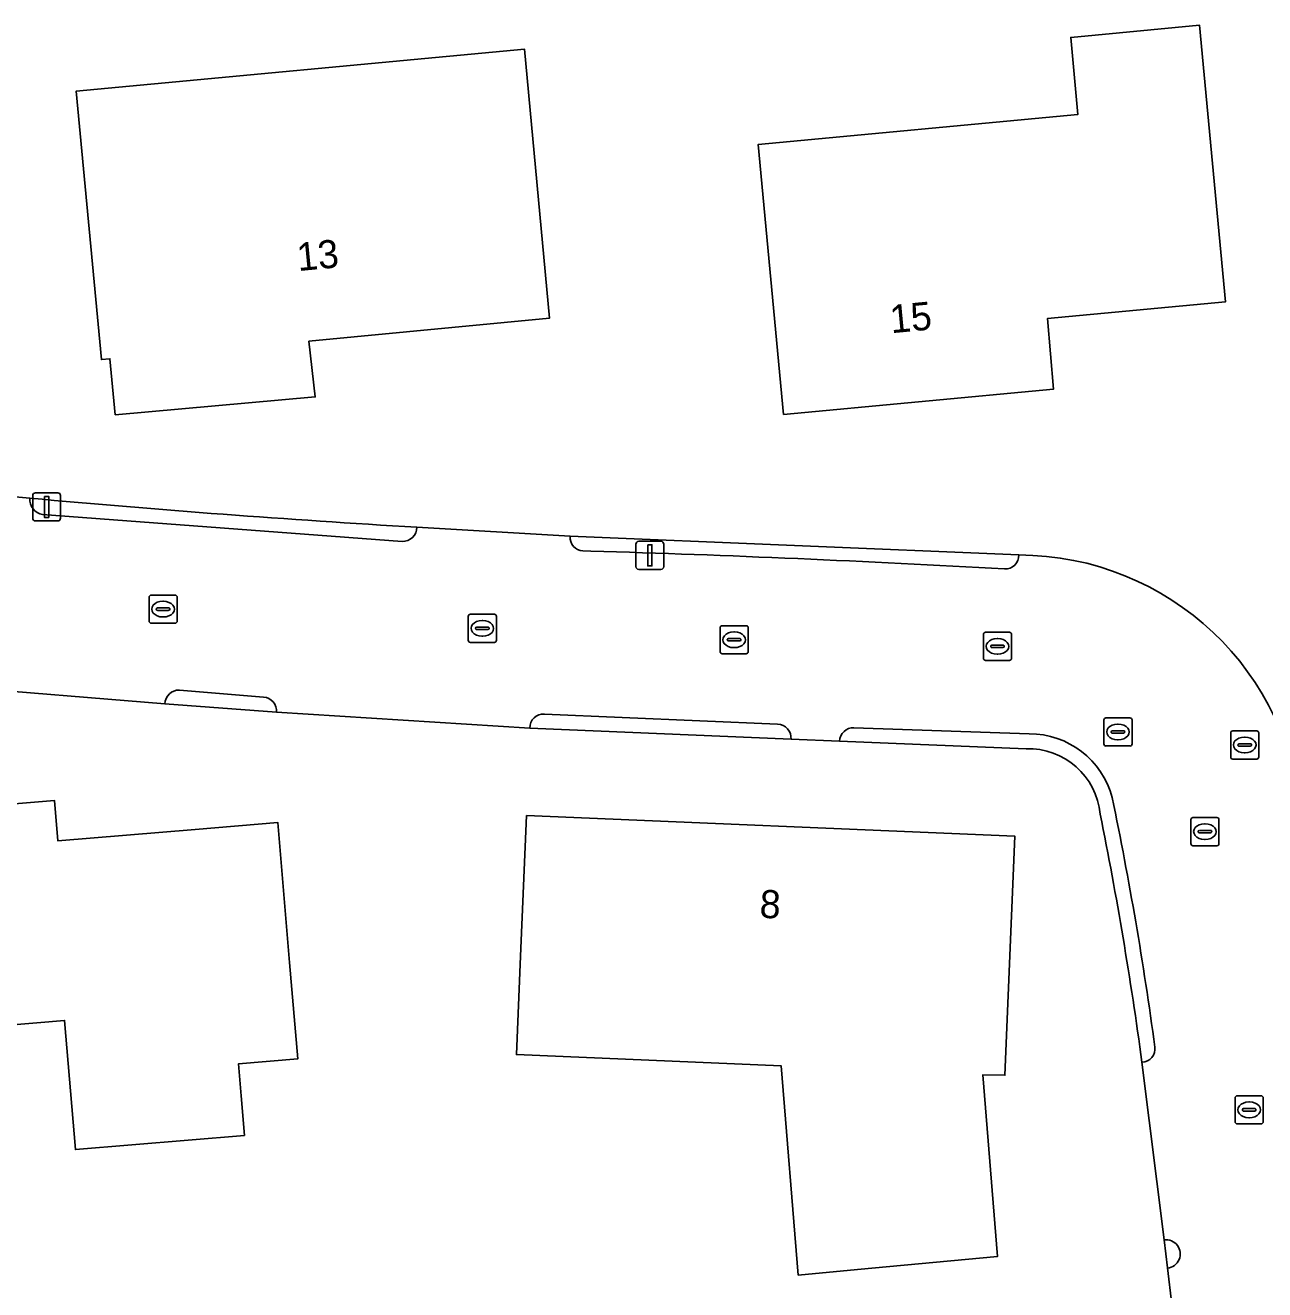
# Model space of a CAD drawing. Extents: x 162156 to 163172, y 378995 to 380779.
# Drawn here: x 162380.59 to 162424.68, y 380662.76 to 380707.74 of the extents above; entities that cross this region are included whole.
import ezdxf

# ---------------------------------------------------------------- set-up
doc = ezdxf.new("R2010")
doc.units = 0
for name, color, linetype in [('IMGEO_Brandkraan', 7, 'Continuous'), ('IMGEO_Erf', 7, 'Continuous'), ('IMGEO_Kolk', 7, 'Continuous'), ('IMGEO_Lichtmast', 7, 'Continuous'), ('IMGEO_Pand', 7, 'Continuous'), ('IMGEO_Pand_nummerreeks', 7, 'Continuous'), ('IMGEO_Rijbaan_lokaal_open', 7, 'Continuous'), ('IMGEO_Rioolput', 7, 'Continuous'), ('IMGEO_Voetpad_open', 7, 'Continuous')]:
    doc.layers.add(name, color=color, linetype=linetype)

msp = doc.modelspace()

# ---------------------------------------------------------------- linework, layer by layer
at = {"layer": 'IMGEO_Brandkraan'}
for p, q in [((162423.466, 380681.714), (162423.466, 380682.566)), ((162423.541, 380682.64), (162424.393, 380682.64)), ((162423.954, 380682.42), (162423.979, 380682.42)), ((162424.467, 380682.566), (162424.467, 380681.714)), ((162423.725, 380682.134), (162423.725, 380682.146)), ((162424.163, 380682.097), (162423.765, 380682.097)), ((162423.768, 380682.183), (162424.166, 380682.183)), ((162423.977, 380681.86), (162423.952, 380681.86)), ((162424.209, 380682.146), (162424.209, 380682.134)), ((162424.393, 380681.64), (162423.541, 380681.64))]:
    msp.add_line(p, q, dxfattribs=at)
for points in [[(162423.466, 380681.714), (162423.466, 380682.566)], [(162423.541, 380682.64), (162424.393, 380682.64)], [(162424.467, 380682.566), (162424.467, 380681.714)], [(162424.393, 380681.64), (162423.541, 380681.64)]]:
    msp.add_lwpolyline(points, dxfattribs=at)
for centre, radius, start, end in [((162423.543, 380682.564), 0.0765, 91.552, 178.448), ((162423.543, 380682.564), 0.0765, 91.552, 178.448), ((162424.391, 380682.564), 0.0765, 1.552, 88.448), ((162424.391, 380682.564), 0.0765, 1.552, 88.448), ((162423.765, 380682.143), 0.0403, 85.8775, 175.7526), ((162423.762, 380682.133), 0.0366, 178.938, 274.7102), ((162424.166, 380682.14), 0.043, 264.8664, 352.4533), ((162424.17, 380682.145), 0.0386, 1.7309, 96.639), ((162423.543, 380681.716), 0.0765, 181.552, 268.448), ((162423.543, 380681.716), 0.0765, 181.552, 268.448), ((162424.391, 380681.716), 0.0765, 271.552, 358.448), ((162424.391, 380681.716), 0.0765, 271.552, 358.448)]:
    msp.add_arc(centre, radius, start, end, dxfattribs=at)
for centre, major_axis, ratio, start_param, end_param in [((162423.953, 380682.14), (-0.387, 0.002), 0.722429, 4.712389, 7.853982), ((162423.978, 380682.14), (-0.39, 0.002), 0.717154, 1.570796, 4.712389)]:
    msp.add_ellipse(centre, major_axis=major_axis, ratio=ratio, start_param=start_param, end_param=end_param, dxfattribs=at)
at = {"layer": 'IMGEO_Erf'}
for points in [[(162407.558, 380693.891), (162406.654, 380703.498), (162418.034, 380704.571), (162417.777, 380707.309), (162422.357, 380707.741), (162423.284, 380697.905), (162416.947, 380697.307), (162417.161, 380694.796)], [(162383.783, 380693.889), (162383.596, 380695.878), (162383.297, 380695.85), (162382.401, 380705.401), (162398.341, 380706.895), (162399.237, 380697.323), (162390.677, 380696.5), (162390.903, 380694.519)], [(162370.147, 380671.342), (162369.798, 380675.489), (162369.378, 380680.471), (162377.536, 380681.174), (162377.649, 380679.832), (162381.627, 380680.167), (162381.749, 380678.726), (162386.632, 380679.138), (162389.571, 380679.386), (162389.991, 380674.404), (162390.28, 380670.974), (162388.167, 380670.796), (162388.262, 380669.663), (162388.382, 380668.252), (162382.372, 380667.746), (162381.985, 380672.339)], [(162407.472, 380670.727), (162398.06, 380671.123), (162398.208, 380674.63), (162398.418, 380679.625), (162415.79, 380678.893), (162415.435, 380670.393), (162414.646, 380670.4), (162415.167, 380663.941), (162410.189, 380663.479), (162408.083, 380663.283)]]:
    msp.add_lwpolyline(points, close=True, dxfattribs=at)
for points in [[(162376.382, 380691.307), (162380.755, 380690.919)], [(162394.515, 380689.886), (162399.974, 380689.562), (162415.928, 380688.898)], [(162416.186, 380682.008), (162409.556, 380682.276), (162407.826, 380682.346), (162398.541, 380682.743), (162389.525, 380683.301), (162385.556, 380683.6), (162378.006, 380684.221)], [(162421.368, 380662.235), (162421.22, 380663.534), (162421.1, 380664.53), (162420.311, 380670.851)]]:
    msp.add_lwpolyline(points, dxfattribs=at)
for centre, radius, start, end in [((162419.09, 381109.397), 420.23, 264.76598, 266.64743), ((162415.913, 380678.811), 10.087, 3.3743, 89.9136), ((162416.259, 380679.433), 2.576, 5.4978, 91.6247), ((162284.383, 380652.482), 137.163, 7.69611, 11.43684)]:
    msp.add_arc(centre, radius, start, end, dxfattribs=at)
at = {"layer": 'IMGEO_Kolk'}
for p, q in [((162384.99, 380686.546), (162384.99, 380687.398)), ((162385.065, 380687.472), (162385.917, 380687.472)), ((162385.478, 380687.252), (162385.503, 380687.252)), ((162385.991, 380687.398), (162385.991, 380686.546)), ((162385.249, 380686.966), (162385.249, 380686.978)), ((162385.687, 380686.929), (162385.289, 380686.929)), ((162385.292, 380687.015), (162385.69, 380687.015)), ((162385.733, 380686.978), (162385.733, 380686.966)), ((162396.422, 380686.788), (162397.274, 380686.788)), ((162385.917, 380686.472), (162385.065, 380686.472)), ((162385.501, 380686.692), (162385.476, 380686.692)), ((162396.347, 380685.862), (162396.347, 380686.714)), ((162396.606, 380686.282), (162396.606, 380686.294)), ((162396.649, 380686.331), (162397.047, 380686.331)), ((162396.835, 380686.568), (162396.86, 380686.568)), ((162397.09, 380686.294), (162397.09, 380686.282)), ((162397.348, 380686.714), (162397.348, 380685.862)), ((162405.302, 380685.456), (162405.302, 380686.308)), ((162405.377, 380686.382), (162406.229, 380686.382)), ((162406.303, 380686.308), (162406.303, 380685.456)), ((162397.044, 380686.245), (162396.646, 380686.245)), ((162396.858, 380686.008), (162396.833, 380686.008)), ((162405.561, 380685.876), (162405.561, 380685.888)), ((162405.999, 380685.839), (162405.601, 380685.839)), ((162405.604, 380685.925), (162406.002, 380685.925)), ((162405.79, 380686.162), (162405.815, 380686.162)), ((162406.045, 380685.888), (162406.045, 380685.876)), ((162414.67, 380685.221), (162414.67, 380686.073)), ((162414.745, 380686.147), (162415.597, 380686.147)), ((162415.158, 380685.927), (162415.183, 380685.927)), ((162415.671, 380686.073), (162415.671, 380685.221)), ((162397.274, 380685.788), (162396.422, 380685.788)), ((162406.229, 380685.382), (162405.377, 380685.382)), ((162405.813, 380685.602), (162405.788, 380685.602)), ((162414.929, 380685.641), (162414.929, 380685.653)), ((162415.367, 380685.604), (162414.969, 380685.604)), ((162414.972, 380685.69), (162415.37, 380685.69)), ((162415.181, 380685.367), (162415.156, 380685.367)), ((162415.413, 380685.653), (162415.413, 380685.641)), ((162415.597, 380685.147), (162414.745, 380685.147)), ((162422.124, 380679.557), (162422.976, 380679.557)), ((162422.049, 380678.631), (162422.049, 380679.483)), ((162422.351, 380679.1), (162422.749, 380679.1)), ((162422.537, 380679.337), (162422.562, 380679.337)), ((162423.05, 380679.483), (162423.05, 380678.631)), ((162422.308, 380679.051), (162422.308, 380679.063)), ((162422.746, 380679.014), (162422.348, 380679.014)), ((162422.56, 380678.777), (162422.535, 380678.777)), ((162422.792, 380679.063), (162422.792, 380679.051)), ((162422.976, 380678.557), (162422.124, 380678.557)), ((162423.698, 380669.66), (162424.55, 380669.66)), ((162423.623, 380668.734), (162423.623, 380669.586)), ((162423.925, 380669.203), (162424.323, 380669.203)), ((162424.111, 380669.44), (162424.136, 380669.44)), ((162424.624, 380669.586), (162424.624, 380668.734)), ((162423.882, 380669.154), (162423.882, 380669.166)), ((162424.32, 380669.117), (162423.922, 380669.117)), ((162424.134, 380668.88), (162424.109, 380668.88)), ((162424.366, 380669.166), (162424.366, 380669.154)), ((162424.55, 380668.66), (162423.698, 380668.66))]:
    msp.add_line(p, q, dxfattribs=at)
for points in [[(162384.99, 380686.546), (162384.99, 380687.398)], [(162385.065, 380687.472), (162385.917, 380687.472)], [(162385.991, 380687.398), (162385.991, 380686.546)], [(162396.422, 380686.788), (162397.274, 380686.788)], [(162385.917, 380686.472), (162385.065, 380686.472)], [(162396.347, 380685.862), (162396.347, 380686.714)], [(162397.348, 380686.714), (162397.348, 380685.862)], [(162405.302, 380685.456), (162405.302, 380686.308)], [(162405.377, 380686.382), (162406.229, 380686.382)], [(162406.303, 380686.308), (162406.303, 380685.456)], [(162414.67, 380685.221), (162414.67, 380686.073)], [(162414.745, 380686.147), (162415.597, 380686.147)], [(162415.671, 380686.073), (162415.671, 380685.221)], [(162397.274, 380685.788), (162396.422, 380685.788)], [(162406.229, 380685.382), (162405.377, 380685.382)], [(162415.597, 380685.147), (162414.745, 380685.147)], [(162422.124, 380679.557), (162422.976, 380679.557)], [(162422.049, 380678.631), (162422.049, 380679.483)], [(162423.05, 380679.483), (162423.05, 380678.631)], [(162422.976, 380678.557), (162422.124, 380678.557)], [(162423.698, 380669.66), (162424.55, 380669.66)], [(162423.623, 380668.734), (162423.623, 380669.586)], [(162424.624, 380669.586), (162424.624, 380668.734)], [(162424.55, 380668.66), (162423.698, 380668.66)]]:
    msp.add_lwpolyline(points, dxfattribs=at)
for centre, radius, start, end in [((162385.067, 380687.396), 0.0765, 91.552, 178.448), ((162385.067, 380687.396), 0.0765, 91.552, 178.448), ((162385.915, 380687.396), 0.0765, 1.552, 88.448), ((162385.915, 380687.396), 0.0765, 1.552, 88.448), ((162385.289, 380686.975), 0.0403, 85.8775, 175.7526), ((162385.286, 380686.965), 0.0366, 178.938, 274.7102), ((162385.69, 380686.972), 0.043, 264.8664, 352.4533), ((162385.694, 380686.977), 0.0386, 1.7309, 96.639), ((162396.424, 380686.712), 0.0765, 91.552, 178.448), ((162396.424, 380686.712), 0.0765, 91.552, 178.448), ((162397.272, 380686.712), 0.0765, 1.552, 88.448), ((162397.272, 380686.712), 0.0765, 1.552, 88.448), ((162385.067, 380686.548), 0.0765, 181.552, 268.448), ((162385.067, 380686.548), 0.0765, 181.552, 268.448), ((162385.915, 380686.548), 0.0765, 271.552, 358.448), ((162385.915, 380686.548), 0.0765, 271.552, 358.448), ((162396.646, 380686.291), 0.0403, 85.8775, 175.7526), ((162396.643, 380686.281), 0.0366, 178.938, 274.7102), ((162397.047, 380686.288), 0.043, 264.8664, 352.4533), ((162397.051, 380686.293), 0.0386, 1.7309, 96.639), ((162405.379, 380686.306), 0.0765, 91.552, 178.448), ((162405.379, 380686.306), 0.0765, 91.552, 178.448), ((162406.227, 380686.306), 0.0765, 1.552, 88.448), ((162406.227, 380686.306), 0.0765, 1.552, 88.448), ((162396.424, 380685.864), 0.0765, 181.552, 268.448), ((162396.424, 380685.864), 0.0765, 181.552, 268.448), ((162397.272, 380685.864), 0.0765, 271.552, 358.448), ((162397.272, 380685.864), 0.0765, 271.552, 358.448), ((162405.601, 380685.885), 0.0403, 85.8775, 175.7526), ((162405.598, 380685.875), 0.0366, 178.938, 274.7102), ((162406.002, 380685.882), 0.043, 264.8664, 352.4533), ((162406.006, 380685.887), 0.0386, 1.7309, 96.639), ((162414.747, 380686.071), 0.0765, 91.552, 178.448), ((162414.747, 380686.071), 0.0765, 91.552, 178.448), ((162415.595, 380686.071), 0.0765, 1.552, 88.448), ((162415.595, 380686.071), 0.0765, 1.552, 88.448), ((162405.379, 380685.458), 0.0765, 181.552, 268.448), ((162405.379, 380685.458), 0.0765, 181.552, 268.448), ((162406.227, 380685.458), 0.0765, 271.552, 358.448), ((162406.227, 380685.458), 0.0765, 271.552, 358.448), ((162414.969, 380685.65), 0.0403, 85.8775, 175.7526), ((162414.966, 380685.64), 0.0366, 178.938, 274.7102), ((162415.37, 380685.647), 0.043, 264.8664, 352.4533), ((162415.374, 380685.652), 0.0386, 1.7309, 96.639), ((162414.747, 380685.223), 0.0765, 181.552, 268.448), ((162414.747, 380685.223), 0.0765, 181.552, 268.448), ((162415.595, 380685.223), 0.0765, 271.552, 358.448), ((162415.595, 380685.223), 0.0765, 271.552, 358.448), ((162422.126, 380679.481), 0.0765, 91.552, 178.448), ((162422.126, 380679.481), 0.0765, 91.552, 178.448), ((162422.974, 380679.481), 0.0765, 1.552, 88.448), ((162422.974, 380679.481), 0.0765, 1.552, 88.448), ((162422.348, 380679.06), 0.0403, 85.8775, 175.7526), ((162422.753, 380679.062), 0.0386, 1.7309, 96.639), ((162422.126, 380678.633), 0.0765, 181.552, 268.448), ((162422.126, 380678.633), 0.0765, 181.552, 268.448), ((162422.345, 380679.05), 0.0366, 178.938, 274.7102), ((162422.749, 380679.057), 0.043, 264.8664, 352.4533), ((162422.974, 380678.633), 0.0765, 271.552, 358.448), ((162422.974, 380678.633), 0.0765, 271.552, 358.448), ((162423.7, 380669.584), 0.0765, 91.552, 178.448), ((162423.7, 380669.584), 0.0765, 91.552, 178.448), ((162424.548, 380669.584), 0.0765, 1.552, 88.448), ((162424.548, 380669.584), 0.0765, 1.552, 88.448), ((162423.922, 380669.163), 0.0403, 85.8775, 175.7526), ((162424.327, 380669.165), 0.0386, 1.7309, 96.639), ((162423.7, 380668.736), 0.0765, 181.552, 268.448), ((162423.7, 380668.736), 0.0765, 181.552, 268.448), ((162423.919, 380669.153), 0.0366, 178.938, 274.7102), ((162424.323, 380669.16), 0.043, 264.8664, 352.4533), ((162424.548, 380668.736), 0.0765, 271.552, 358.448), ((162424.548, 380668.736), 0.0765, 271.552, 358.448)]:
    msp.add_arc(centre, radius, start, end, dxfattribs=at)
for centre, major_axis, ratio, start_param, end_param in [((162385.477, 380686.972), (-0.387, 0.002), 0.722429, 4.712389, 7.853982), ((162385.502, 380686.972), (-0.39, 0.002), 0.717154, 1.570796, 4.712389), ((162396.834, 380686.288), (-0.387, 0.002), 0.722429, 4.712389, 7.853982), ((162396.859, 380686.288), (-0.39, 0.002), 0.717154, 1.570796, 4.712389), ((162405.789, 380685.882), (-0.387, 0.002), 0.722429, 4.712389, 7.853982), ((162405.814, 380685.882), (-0.39, 0.002), 0.717154, 1.570796, 4.712389), ((162415.157, 380685.647), (-0.387, 0.002), 0.722429, 4.712389, 7.853982), ((162415.182, 380685.647), (-0.39, 0.002), 0.717154, 1.570796, 4.712389), ((162422.536, 380679.057), (-0.387, 0.002), 0.722429, 4.712389, 7.853982), ((162422.561, 380679.057), (-0.39, 0.002), 0.717154, 1.570796, 4.712389), ((162424.11, 380669.16), (-0.387, 0.002), 0.722429, 4.712389, 7.853982), ((162424.135, 380669.16), (-0.39, 0.002), 0.717154, 1.570796, 4.712389)]:
    msp.add_ellipse(centre, major_axis=major_axis, ratio=ratio, start_param=start_param, end_param=end_param, dxfattribs=at)
at = {"layer": 'IMGEO_Lichtmast'}
for p, q in [((162380.851, 380690.209), (162380.851, 380691.009)), ((162380.851, 380691.009), (162380.851, 380690.209)), ((162380.951, 380691.109), (162381.741, 380691.109)), ((162381.741, 380691.109), (162380.951, 380691.109)), ((162381.841, 380691.009), (162381.841, 380690.209)), ((162381.841, 380690.209), (162381.841, 380691.009)), ((162381.741, 380690.109), (162380.951, 380690.109)), ((162380.951, 380690.109), (162381.741, 380690.109)), ((162402.309, 380688.485), (162402.309, 380689.285)), ((162402.309, 380689.285), (162402.309, 380688.485)), ((162402.409, 380689.385), (162403.199, 380689.385)), ((162403.199, 380689.385), (162402.409, 380689.385)), ((162403.299, 380689.285), (162403.299, 380688.485)), ((162403.299, 380688.485), (162403.299, 380689.285)), ((162403.199, 380688.385), (162402.409, 380688.385)), ((162402.409, 380688.385), (162403.199, 380688.385))]:
    msp.add_line(p, q, dxfattribs=at)
for points in [[(162381.271, 380690.984), (162381.421, 380690.984), (162381.421, 380690.234), (162381.271, 380690.234), (162381.271, 380690.984)], [(162402.729, 380689.26), (162402.879, 380689.26), (162402.879, 380688.51), (162402.729, 380688.51), (162402.729, 380689.26)]]:
    msp.add_lwpolyline(points, dxfattribs=at)
for centre, start, end in [((162380.951, 380691.009), 90, 180), ((162380.951, 380691.009), 90, 180), ((162381.741, 380691.009), 0, 90), ((162381.741, 380691.009), 360, 90), ((162380.951, 380690.209), 180, 270), ((162380.951, 380690.209), 180, 270), ((162381.741, 380690.209), 270, 0), ((162381.741, 380690.209), 270, 0), ((162402.409, 380689.285), 90, 180), ((162402.409, 380689.285), 90, 180), ((162403.199, 380689.285), 0, 90), ((162403.199, 380689.285), 360, 90), ((162402.409, 380688.485), 180, 270), ((162402.409, 380688.485), 180, 270), ((162403.199, 380688.485), 270, 0), ((162403.199, 380688.485), 270, 0)]:
    msp.add_arc(centre, 0.1, start, end, dxfattribs=at)
at = {"layer": 'IMGEO_Pand'}
for points in [[(162407.558, 380693.891), (162417.161, 380694.796), (162416.947, 380697.307), (162423.284, 380697.905), (162422.357, 380707.741), (162417.777, 380707.309), (162418.034, 380704.571), (162406.654, 380703.498)], [(162383.783, 380693.889), (162390.903, 380694.519), (162390.677, 380696.5), (162399.237, 380697.323), (162398.341, 380706.895), (162382.401, 380705.401), (162383.297, 380695.85), (162383.596, 380695.878)], [(162389.571, 380679.386), (162386.632, 380679.138), (162381.749, 380678.726), (162381.627, 380680.167), (162377.649, 380679.832), (162377.536, 380681.174), (162369.378, 380680.471), (162369.798, 380675.489), (162370.147, 380671.342), (162381.985, 380672.339), (162382.372, 380667.746), (162388.382, 380668.252), (162388.262, 380669.663), (162388.167, 380670.796), (162390.28, 380670.974), (162389.991, 380674.404)], [(162410.189, 380663.479), (162415.167, 380663.941), (162414.646, 380670.4), (162415.435, 380670.393), (162415.79, 380678.893), (162398.418, 380679.625), (162398.208, 380674.63), (162398.06, 380671.123), (162407.472, 380670.727), (162408.083, 380663.283)]]:
    msp.add_lwpolyline(points, close=True, dxfattribs=at)
at = {"layer": 'IMGEO_Rijbaan_lokaal_open'}
for points in [[(162380.755, 380690.919), (162376.382, 380691.307)], [(162393.99, 380689.38), (162381.204, 380690.341)], [(162399.974, 380689.562), (162394.515, 380689.886)], [(162400.703, 380689.034), (162400.421, 380689.042)], [(162378.006, 380684.221), (162385.556, 380683.6)], [(162386.073, 380684.093), (162389.066, 380683.843)], [(162389.525, 380683.301), (162398.541, 380682.743)], [(162399.052, 380683.24), (162407.351, 380682.877)], [(162410.064, 380682.749), (162416.296, 380682.536)], [(162407.826, 380682.346), (162409.556, 380682.276)], [(162420.311, 380670.851), (162421.1, 380664.53)], [(162421.22, 380663.534), (162421.368, 380662.235)]]:
    msp.add_lwpolyline(points, dxfattribs=at)
for centre, radius, start, end in [((162381.277, 380690.861), 0.525, 173.6353, 262.046), ((162394.016, 380689.879), 0.499, 267.0637, 0.8248), ((162400.445, 380689.514), 0.473, 174.231, 267.1348), ((162385.187, 380157.58), 531.681, 86.73986, 88.32766), ((162415.447, 380688.881), 0.481, 267.1318, 2.0684), ((162415.913, 380678.811), 10.087, 3.3743, 89.9136), ((162386.063, 380683.586), 0.507, 88.8668, 178.4107), ((162389.029, 380683.346), 0.499, 354.8314, 85.6887), ((162399.016, 380682.765), 0.476, 85.7087, 182.6999), ((162407.338, 380682.387), 0.49, 355.1429, 88.4849), ((162410.043, 380682.263), 0.487, 87.492, 178.4214), ((162416.305, 380679.486), 3.05, 14.8388, 90.1608), ((162292.222, 380653.966), 129.725, 7.72117, 11.69742), ((162420.287, 380671.338), 0.488, 272.8393, 6.7258), ((162421.17, 380664.033), 0.502, 275.7337, 98.0063)]:
    msp.add_arc(centre, radius, start, end, dxfattribs=at)
at = {"layer": 'IMGEO_Rioolput'}
for p, q in [((162418.955, 380682.177), (162418.955, 380683.029)), ((162419.03, 380683.103), (162419.882, 380683.103)), ((162419.443, 380682.883), (162419.468, 380682.883)), ((162419.956, 380683.029), (162419.956, 380682.177)), ((162419.214, 380682.597), (162419.214, 380682.609)), ((162419.652, 380682.56), (162419.254, 380682.56)), ((162419.257, 380682.646), (162419.655, 380682.646)), ((162419.466, 380682.323), (162419.441, 380682.323)), ((162419.698, 380682.609), (162419.698, 380682.597)), ((162419.882, 380682.103), (162419.03, 380682.103))]:
    msp.add_line(p, q, dxfattribs=at)
for points in [[(162418.955, 380682.177), (162418.955, 380683.029)], [(162419.03, 380683.103), (162419.882, 380683.103)], [(162419.956, 380683.029), (162419.956, 380682.177)], [(162419.882, 380682.103), (162419.03, 380682.103)]]:
    msp.add_lwpolyline(points, dxfattribs=at)
for centre, radius, start, end in [((162419.032, 380683.027), 0.0765, 91.552, 178.448), ((162419.032, 380683.027), 0.0765, 91.552, 178.448), ((162419.88, 380683.027), 0.0765, 1.552, 88.448), ((162419.88, 380683.027), 0.0765, 1.552, 88.448), ((162419.254, 380682.606), 0.0403, 85.8775, 175.7526), ((162419.251, 380682.596), 0.0366, 178.938, 274.7102), ((162419.655, 380682.603), 0.043, 264.8664, 352.4533), ((162419.659, 380682.608), 0.0386, 1.7309, 96.639), ((162419.032, 380682.179), 0.0765, 181.552, 268.448), ((162419.032, 380682.179), 0.0765, 181.552, 268.448), ((162419.88, 380682.179), 0.0765, 271.552, 358.448), ((162419.88, 380682.179), 0.0765, 271.552, 358.448)]:
    msp.add_arc(centre, radius, start, end, dxfattribs=at)
for centre, major_axis, ratio, start_param, end_param in [((162419.442, 380682.603), (-0.387, 0.002), 0.722429, 4.712389, 7.853982), ((162419.467, 380682.603), (-0.39, 0.002), 0.717154, 1.570796, 4.712389)]:
    msp.add_ellipse(centre, major_axis=major_axis, ratio=ratio, start_param=start_param, end_param=end_param, dxfattribs=at)
at = {"layer": 'IMGEO_Voetpad_open'}
for points in [[(162381.204, 380690.341), (162393.99, 380689.38)], [(162415.928, 380688.898), (162399.974, 380689.562)], [(162400.421, 380689.042), (162400.703, 380689.034)], [(162389.066, 380683.843), (162386.073, 380684.093)], [(162385.556, 380683.6), (162389.525, 380683.301)], [(162407.351, 380682.877), (162399.052, 380683.24)], [(162398.541, 380682.743), (162407.826, 380682.346)], [(162416.296, 380682.536), (162410.064, 380682.749)], [(162409.556, 380682.276), (162416.186, 380682.008)], [(162421.1, 380664.53), (162421.22, 380663.534)]]:
    msp.add_lwpolyline(points, dxfattribs=at)
for centre, radius, start, end in [((162381.277, 380690.861), 0.525, 173.6353, 262.046), ((162419.09, 381109.397), 420.23, 264.76598, 266.64743), ((162394.016, 380689.879), 0.499, 267.0637, 0.8248), ((162400.445, 380689.514), 0.473, 174.231, 267.1348), ((162385.187, 380157.58), 531.681, 86.73986, 88.32766), ((162415.447, 380688.881), 0.481, 267.1318, 2.0684), ((162386.063, 380683.586), 0.507, 88.8668, 178.4107), ((162389.029, 380683.346), 0.499, 354.8314, 85.6887), ((162399.016, 380682.765), 0.476, 85.7087, 182.6999), ((162407.338, 380682.387), 0.49, 355.1429, 88.4849), ((162410.043, 380682.263), 0.487, 87.492, 178.4214), ((162416.305, 380679.486), 3.05, 14.8388, 90.1608), ((162416.259, 380679.433), 2.576, 5.4978, 91.6247), ((162292.222, 380653.966), 129.725, 7.72117, 11.69742), ((162284.383, 380652.482), 137.163, 7.69611, 11.43684), ((162420.287, 380671.338), 0.488, 272.8393, 6.7258), ((162421.17, 380664.033), 0.502, 275.7337, 98.0063)]:
    msp.add_arc(centre, radius, start, end, dxfattribs=at)

# ---------------------------------------------------------------- texts
at = {"layer": 'IMGEO_Pand_nummerreeks'}
for s, rotation, p in [('13', 5.4918, (162390.296, 380698.995)), ('15', 5.3837, (162411.39, 380696.784)), ('8', 357.5872, (162406.695, 380675.994))]:
    msp.add_text(s, height=1, rotation=rotation, dxfattribs=at).set_placement(p)

doc.saveas('drawing.dxf')
